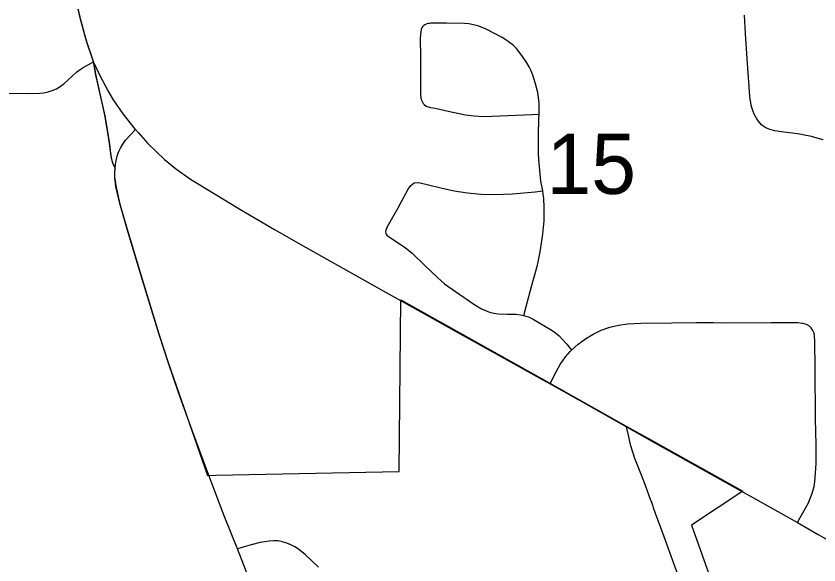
# Model space of a CAD drawing. Extents: x 0 to 34, y 0 to 22.
# Drawn here: x 20.417 to 20.975, y 11.815 to 12.198 of the extents above; entities that cross this region are included whole.
import ezdxf

# ---------------------------------------------------------------- set-up
doc = ezdxf.new("R2010")
doc.units = 0
for name, color, linetype in [('GM_X_City_Street', 7, 'Continuous'), ('GM_X_Corporation', 7, 'Continuous'), ('GM_X_Interchange_Ramps', 7, 'Continuous'), ('GM_X_Section_Text', 7, 'Continuous'), ('GM_X_State_Route', 7, 'Continuous'), ('GM_X_Township_Road', 7, 'Continuous')]:
    doc.layers.add(name, color=color, linetype=linetype)

msp = doc.modelspace()

# ---------------------------------------------------------------- linework, layer by layer
at = {"layer": 'GM_X_City_Street'}
for points in [[(20.97828, 12.11145), (20.96938, 12.11381), (20.96637, 12.11444), (20.96325, 12.11498), (20.96043, 12.11547), (20.95701, 12.11593), (20.9509, 12.1167), (20.94777, 12.11706), (20.94462, 12.11766), (20.94116, 12.11859), (20.93951, 12.11918), (20.93786, 12.12), (20.93544, 12.12183), (20.93321, 12.12437), (20.9321, 12.126), (20.93114, 12.12761), (20.93031, 12.12931), (20.92962, 12.13102), (20.92826, 12.13538), (20.92791, 12.13733), (20.92761, 12.13939), (20.92717, 12.14482), (20.92661, 12.15187), (20.92613, 12.15782), (20.92437, 12.18511), (20.92353, 12.1981)], [(20.77005, 11.98906), (20.77143, 11.99429), (20.77539, 12.00919), (20.77947, 12.02415), (20.78143, 12.03327), (20.78333, 12.04556), (20.78407, 12.05487), (20.7842, 12.06417), (20.78394, 12.07044), (20.78353, 12.07356), (20.78314, 12.07574), (20.78193, 12.08268), (20.78075, 12.09494), (20.78029, 12.10106), (20.78013, 12.11479), (20.78049, 12.12569), (20.78061, 12.12931), (20.7807, 12.13191), (20.78063, 12.13666), (20.7803, 12.14094), (20.7797, 12.14441), (20.77817, 12.15047), (20.77626, 12.15643), (20.77507, 12.15935), (20.77368, 12.16218), (20.77214, 12.16488), (20.76872, 12.17008), (20.76485, 12.17502), (20.76259, 12.17728), (20.76012, 12.17927), (20.75756, 12.18109), (20.75487, 12.18273), (20.74386, 12.18846), (20.74096, 12.18968), (20.73799, 12.19072), (20.73492, 12.19155), (20.73179, 12.19209), (20.72865, 12.19237), (20.71623, 12.19257), (20.70558, 12.19252), (20.70451, 12.19247), (20.70329, 12.19231), (20.70204, 12.19198), (20.70102, 12.19151), (20.70033, 12.19095), (20.69978, 12.1904), (20.69931, 12.18977), (20.69858, 12.18821), (20.69803, 12.1849), (20.69791, 12.18176), (20.69807, 12.16935), (20.69814, 12.15796), (20.69812, 12.157)], [(20.69812, 12.157), (20.69803, 12.14248), (20.69849, 12.13944), (20.69988, 12.13676), (20.70064, 12.1359), (20.70196, 12.13492), (20.70518, 12.13391), (20.70824, 12.13336), (20.71726, 12.13125), (20.72938, 12.12884), (20.73551, 12.12806), (20.74166, 12.12766), (20.74783, 12.12774), (20.7756, 12.12907), (20.78061, 12.12931)], [(20.68331, 12.06547), (20.68958, 12.07695), (20.69136, 12.07957), (20.69381, 12.08144), (20.69689, 12.0816), (20.71221, 12.07792), (20.72144, 12.0759), (20.73075, 12.07434), (20.74016, 12.07351), (20.7496, 12.07329), (20.76218, 12.07382), (20.77785, 12.07526), (20.78314, 12.07574)], [(20.68331, 12.06547), (20.67489, 12.05075), (20.67435, 12.04958), (20.67401, 12.04838), (20.67383, 12.04738), (20.67393, 12.04639), (20.6742, 12.04571), (20.67469, 12.04505), (20.67716, 12.04318), (20.68754, 12.03639), (20.6923, 12.03243), (20.70124, 12.02384), (20.71008, 12.01514), (20.71483, 12.01118), (20.72236, 12.00573), (20.73515, 11.99696), (20.74046, 11.99375), (20.74326, 11.99242), (20.74617, 11.99137), (20.74918, 11.99063), (20.75225, 11.99022), (20.75845, 11.99001), (20.76465, 11.98993), (20.76773, 11.98959), (20.77005, 11.98906), (20.77075, 11.98889), (20.77363, 11.98779), (20.77641, 11.98641), (20.78985, 11.97863), (20.79207, 11.97699), (20.79471, 11.97487), (20.79676, 11.97256), (20.79996, 11.96909), (20.80329, 11.96482)], [(20.78824, 11.94138), (20.79042, 11.94574), (20.79272, 11.95035), (20.79537, 11.95496), (20.799, 11.96011), (20.80226, 11.96383), (20.80329, 11.96482), (20.80776, 11.96912), (20.81284, 11.97282), (20.81824, 11.97603), (20.82392, 11.97872), (20.82986, 11.9808), (20.83595, 11.98235), (20.84217, 11.98328), (20.85153, 11.98378), (20.87297, 11.98394), (20.89011, 11.98417), (20.9019, 11.98404), (20.90802, 11.98382), (20.94209, 11.98405), (20.95764, 11.9842), (20.96076, 11.98408), (20.9639, 11.98377), (20.96656, 11.98298), (20.96864, 11.98189)], [(20.96041, 11.8448), (20.96236, 11.8483), (20.96778, 11.85799), (20.97024, 11.86383), (20.97124, 11.86671), (20.97207, 11.86984), (20.97248, 11.87309), (20.97308, 11.8794), (20.97334, 11.88569), (20.9734, 11.89822), (20.97322, 11.90864), (20.97308, 11.91638), (20.97288, 11.92773), (20.9728, 11.94171), (20.97275, 11.95125), (20.9727, 11.95917), (20.9726, 11.96426), (20.97245, 11.9712), (20.97234, 11.97453), (20.97201, 11.97665), (20.97124, 11.97856), (20.96993, 11.98049), (20.96864, 11.98189)]]:
    msp.add_lwpolyline(points, dxfattribs=at)
at = {"layer": 'GM_X_Corporation'}
msp.add_lwpolyline([(20.45616, 12.21768), (20.4612, 12.19593), (20.46497, 12.18223), (20.46655, 12.17716), (20.46865, 12.17105), (20.47026, 12.16623), (20.47167, 12.15757), (20.47551, 12.14104), (20.47686, 12.13501), (20.47829, 12.12865), (20.48049, 12.11489), (20.48137, 12.1087), (20.48208, 12.10348), (20.48252, 12.10036), (20.48283, 12.09873), (20.48333, 12.09689), (20.48389, 12.09535), (20.48433, 12.0943), (20.48533, 12.09209), (20.4852, 12.08854), (20.48528, 12.08552), (20.48599, 12.07949), (20.48698, 12.07515), (20.48874, 12.06751), (20.49378, 12.04973), (20.50436, 12.01425), (20.50692, 12.00599), (20.51613, 11.97626), (20.52257, 11.95627), (20.54996, 11.87764), (20.55578, 11.87778), (20.68322, 11.8803), (20.68448, 11.99984), (20.78803, 11.94193), (20.84128, 11.91204), (20.85878, 11.90215), (20.92241, 11.86658), (20.88661, 11.843), (20.88661, 11.843), (20.90113, 11.80255)], dxfattribs=at)
at = {"layer": 'GM_X_Interchange_Ramps'}
msp.add_lwpolyline([(20.47047, 12.16569), (20.47188, 12.15702), (20.47572, 12.14049), (20.4785, 12.12809), (20.4807, 12.11434), (20.48158, 12.10815), (20.48273, 12.09982), (20.48304, 12.09818), (20.48354, 12.09634), (20.4841, 12.0948), (20.48454, 12.09376), (20.48554, 12.09154)], dxfattribs=at)
at = {"layer": 'GM_X_State_Route'}
msp.add_line((20.49981, 12.11854), (20.50179, 12.1163), dxfattribs=at)
for points in [[(20.47047, 12.16569), (20.46886, 12.1705), (20.46676, 12.17662), (20.46518, 12.18169), (20.46141, 12.19538), (20.45637, 12.21714), (20.4556, 12.22045), (20.44955, 12.24684), (20.44687, 12.25848), (20.43795, 12.29765), (20.43407, 12.31437), (20.424, 12.35744), (20.41536, 12.39402), (20.40571, 12.43493), (20.40453, 12.44031)], [(20.49981, 12.11854), (20.49115, 12.12955), (20.4845, 12.13922), (20.48054, 12.14587), (20.47548, 12.15554), (20.47047, 12.16569)], [(20.48554, 12.09154), (20.48579, 12.09407), (20.48625, 12.09706), (20.48695, 12.09997), (20.48798, 12.10274), (20.48925, 12.10551), (20.4909, 12.10826), (20.4919, 12.10975), (20.49293, 12.11105), (20.49981, 12.11854)], [(20.50179, 12.1163), (20.50839, 12.10884), (20.51997, 12.09768), (20.52768, 12.09144), (20.53805, 12.08392), (20.57245, 12.06319), (20.59652, 12.04902), (20.61799, 12.03655), (20.67218, 12.00628), (20.68469, 11.99929)], [(20.55167, 11.8753), (20.54747, 11.8864), (20.53795, 11.9121), (20.52975, 11.93543), (20.52278, 11.95573), (20.51634, 11.97572), (20.50457, 12.01371), (20.49399, 12.04918), (20.48895, 12.06696), (20.4862, 12.07894), (20.48549, 12.08497), (20.48541, 12.088), (20.48554, 12.09154)], [(20.68469, 11.99929), (20.72366, 11.97752), (20.78323, 11.94417), (20.78824, 11.94138), (20.81306, 11.92757), (20.84149, 11.9115), (20.85899, 11.9016), (20.92262, 11.86604)], [(20.584, 11.79238), (20.57087, 11.82644), (20.56156, 11.84943), (20.55167, 11.8753)], [(20.92262, 11.86604), (20.92943, 11.86223), (20.96041, 11.8448), (20.97475, 11.8365), (21.00609, 11.81855)]]:
    msp.add_lwpolyline(points, dxfattribs=at)
at = {"layer": 'GM_X_Township_Road'}
for points in [[(20.3512, 12.14353), (20.3616, 12.14352), (20.38132, 12.14363), (20.39533, 12.14373), (20.40233, 12.14379), (20.40946, 12.14384), (20.42501, 12.14373), (20.43325, 12.14381), (20.43596, 12.14417), (20.43895, 12.14479), (20.4419, 12.14565), (20.44472, 12.14688), (20.44738, 12.14846), (20.44984, 12.15034), (20.45897, 12.15862), (20.46125, 12.16042), (20.46331, 12.16175), (20.47047, 12.16569)], [(20.95381, 11.63822), (20.93724, 11.66128), (20.93216, 11.66909), (20.92762, 11.67718), (20.92369, 11.6856), (20.91777, 11.7), (20.90676, 11.72919), (20.8895, 11.77604), (20.87636, 11.81115), (20.86575, 11.83991), (20.86263, 11.84856), (20.86057, 11.85443), (20.85981, 11.85665), (20.859, 11.85887), (20.85824, 11.86094), (20.85711, 11.86413), (20.85394, 11.8725), (20.85094, 11.88015), (20.84731, 11.88939), (20.84577, 11.89374), (20.8443, 11.899), (20.84282, 11.90558), (20.84149, 11.9115)], [(20.62717, 11.81381), (20.61809, 11.82231), (20.6132, 11.82615), (20.61059, 11.82782), (20.60785, 11.8293), (20.605, 11.83053), (20.60204, 11.83145), (20.59897, 11.83196), (20.59587, 11.83209), (20.59277, 11.83193), (20.58663, 11.83094), (20.58036, 11.82938), (20.57529, 11.82791), (20.57087, 11.82644)]]:
    msp.add_lwpolyline(points, dxfattribs=at)

# ---------------------------------------------------------------- texts
at = {"layer": 'GM_X_Section_Text'}
msp.add_text('15', height=0.041856, rotation=0, dxfattribs=at).set_placement((20.78581, 12.0737))

doc.saveas('drawing.dxf')
